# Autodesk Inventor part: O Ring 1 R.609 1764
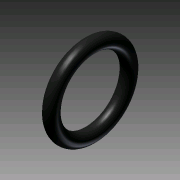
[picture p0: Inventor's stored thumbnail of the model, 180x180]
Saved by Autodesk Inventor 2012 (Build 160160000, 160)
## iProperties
Created: 2007-11
Part Number: O Ring 1 R.609 1764
Document SubType Name: Modeling
Designer: lwoods
Density: 1 g/cm^3
Material: Default
Author: lwoods
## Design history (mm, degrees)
sketch "Sketch1" dims "d0" = 3.175
  geometry: L1 (-29.259, -1.222)-(-5.185, -1.222); L2 (-18.889, 8.1)-(-18.889, 6.512); L3 (-18.889, 6.512)-(-18.889, -1.222)
  constraints: 6 end point, 2 perpendicular, 1 horizontal, 1 point on line, 1 vertical alignment, 2 other
  dimensions: "d1" = 7.7343 distance of L2.end L3.end
revolve "Revolution1" sketch "Sketch1" stored, may be unused: angle "d2" = 90 deg
body "Solid1"
